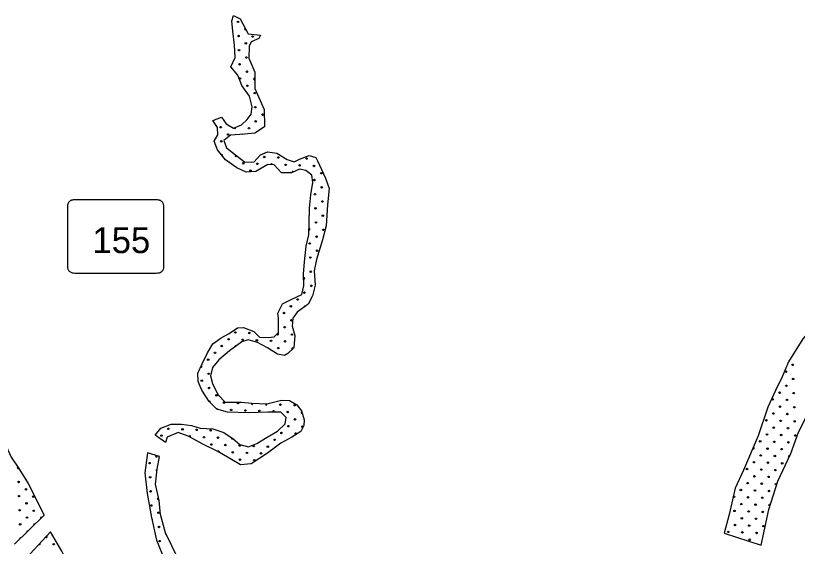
# Model space of a CAD drawing. Extents: x 1612280 to 1883141, y 560852 to 780851.
# Drawn here: x 1712819 to 1723964, y 674507 to 682075 of the extents above; entities that cross this region are included whole.
import ezdxf

# ---------------------------------------------------------------- set-up
doc = ezdxf.new("R2010")
doc.units = 0
for name, color, linetype in [('DESIGN - ROW - Slope Lines', 7, 'Continuous'), ('DESIGN - SCRATCH - User 1', 7, 'Continuous'), ('DESIGN - TRAFFIC CONTROL PERMANENT - Pavement Marking Text', 7, 'Continuous')]:
    doc.layers.add(name, color=color, linetype=linetype)

msp = doc.modelspace()

# ---------------------------------------------------------------- linework, layer by layer
at = {"layer": 'DESIGN - ROW - Slope Lines'}
msp.add_line((1713558, 679346), (1713558, 678515), dxfattribs=at)
msp.add_line((1713558, 679346), (1713558, 678515), dxfattribs=at)
for points in [[(1714931, 679336), (1714931, 679344), (1714931, 679352), (1714930, 679366), (1714929, 679377), (1714927, 679388), (1714925, 679394), (1714922, 679400), (1714917, 679408), (1714912, 679415), (1714907, 679421), (1714901, 679426), (1714897, 679430), (1714890, 679434), (1714885, 679437), (1714877, 679441), (1714871, 679444), (1714864, 679445), (1714854, 679446), (1714846, 679447), (1714837, 679448), (1714825, 679448), (1714816, 679447), (1713658, 679448), (1713649, 679448), (1713639, 679447), (1713630, 679446), (1713621, 679444), (1713616, 679443), (1713609, 679440), (1713603, 679437), (1713597, 679433), (1713588, 679427), (1713582, 679421), (1713577, 679415), (1713573, 679410), (1713568, 679400), (1713564, 679393), (1713562, 679387), (1713562, 679384), (1713561, 679380), (1713560, 679373), (1713559, 679364), (1713559, 679356), (1713559, 679349), (1713558, 679331)], [(1714931, 679336), (1714931, 679344), (1714931, 679352), (1714930, 679366), (1714929, 679377), (1714927, 679388), (1714925, 679394), (1714922, 679400), (1714917, 679408), (1714912, 679415), (1714907, 679421), (1714901, 679426), (1714897, 679430), (1714890, 679434), (1714885, 679437), (1714877, 679441), (1714871, 679444), (1714864, 679445), (1714854, 679446), (1714846, 679447), (1714837, 679448), (1714825, 679448), (1714816, 679447), (1713658, 679448), (1713649, 679448), (1713639, 679447), (1713630, 679446), (1713621, 679444), (1713616, 679443), (1713609, 679440), (1713603, 679437), (1713597, 679433), (1713588, 679427), (1713582, 679421), (1713577, 679415), (1713573, 679410), (1713568, 679400), (1713564, 679393), (1713562, 679387), (1713562, 679384), (1713561, 679380), (1713560, 679373), (1713559, 679364), (1713559, 679356), (1713559, 679349), (1713558, 679331)], [(1714821, 678405), (1714842, 678406), (1714859, 678406), (1714869, 678408), (1714882, 678413), (1714893, 678420), (1714902, 678426), (1714910, 678434), (1714916, 678442), (1714922, 678452), (1714926, 678460), (1714928, 678467), (1714930, 678474), (1714931, 678483), (1714931, 678493), (1714931, 678516), (1714931, 679336)], [(1714821, 678405), (1714842, 678406), (1714859, 678406), (1714869, 678408), (1714882, 678413), (1714893, 678420), (1714902, 678426), (1714910, 678434), (1714916, 678442), (1714922, 678452), (1714926, 678460), (1714928, 678467), (1714930, 678474), (1714931, 678483), (1714931, 678493), (1714931, 678516), (1714931, 679336)], [(1713558, 678515), (1713559, 678506), (1713559, 678495), (1713560, 678486), (1713561, 678477), (1713562, 678468), (1713565, 678460), (1713569, 678453), (1713573, 678445), (1713579, 678438), (1713584, 678432), (1713591, 678425), (1713598, 678420), (1713606, 678415), (1713615, 678411), (1713624, 678408), (1713631, 678407), (1713646, 678406), (1713665, 678405), (1714821, 678405)], [(1713558, 678515), (1713559, 678506), (1713559, 678495), (1713560, 678486), (1713561, 678477), (1713562, 678468), (1713565, 678460), (1713569, 678453), (1713573, 678445), (1713579, 678438), (1713584, 678432), (1713591, 678425), (1713598, 678420), (1713606, 678415), (1713615, 678411), (1713624, 678408), (1713631, 678407), (1713646, 678406), (1713665, 678405), (1714821, 678405)]]:
    msp.add_lwpolyline(points, dxfattribs=at)
at = {"layer": 'DESIGN - SCRATCH - User 1'}
for points in [[(1716413, 679953), (1716242, 679852), (1716105, 679842), (1715971, 679905), (1715809, 680021), (1715697, 680162), (1715651, 680285), (1715704, 680376), (1715697, 680482), (1715630, 680580), (1715753, 680626), (1715820, 680531), (1715925, 680471), (1716038, 680517), (1716119, 680594), (1716178, 680672), (1716193, 680774), (1716154, 680925), (1716045, 681080), (1715985, 681228), (1715887, 681347), (1715950, 681477), (1715939, 681653), (1715915, 681854), (1715901, 682001), (1715925, 682075), (1716020, 682029), (1716136, 681815), (1716312, 681797), (1716287, 681748), (1716178, 681702), (1716147, 681639), (1716143, 681467), (1716231, 681270), (1716231, 681034), (1716361, 680739), (1716365, 680489), (1716231, 680401), (1716084, 680383), (1715883, 680369), (1715788, 680295), (1715827, 680190), (1716080, 679989), (1716217, 679986), (1716308, 680091), (1716409, 680132)], [(1716413, 679953), (1716242, 679852), (1716105, 679842), (1715971, 679905), (1715809, 680021), (1715697, 680162), (1715651, 680285), (1715704, 680376), (1715697, 680482), (1715630, 680580), (1715753, 680626), (1715820, 680531), (1715925, 680471), (1716038, 680517), (1716119, 680594), (1716178, 680672), (1716193, 680774), (1716154, 680925), (1716045, 681080), (1715985, 681228), (1715887, 681347), (1715950, 681477), (1715939, 681653), (1715915, 681854), (1715901, 682001), (1715925, 682075), (1716020, 682029), (1716136, 681815), (1716312, 681797), (1716287, 681748), (1716178, 681702), (1716147, 681639), (1716143, 681467), (1716231, 681270), (1716231, 681034), (1716361, 680739), (1716365, 680489), (1716231, 680401), (1716084, 680383), (1715883, 680369), (1715788, 680295), (1715827, 680190), (1716080, 679989), (1716217, 679986), (1716308, 680091), (1716409, 680132)], [(1716409, 680132), (1716542, 680113), (1716691, 680023), (1716792, 679992), (1716867, 680027), (1717003, 680082), (1717101, 680050), (1717121, 680003), (1717238, 679757), (1717289, 679608), (1717265, 679378), (1717246, 679077), (1717195, 678877), (1717109, 678600), (1717074, 678435), (1717089, 678232), (1717050, 678079), (1716992, 677962), (1716835, 677849), (1716773, 677763), (1716761, 677645), (1716800, 677512), (1716785, 677340), (1716699, 677258), (1716652, 677231), (1716554, 677246), (1716409, 677340)], [(1716409, 680132), (1716542, 680113), (1716691, 680023), (1716792, 679992), (1716867, 680027), (1717003, 680082), (1717101, 680050), (1717121, 680003), (1717238, 679757), (1717289, 679608), (1717265, 679378), (1717246, 679077), (1717195, 678877), (1717109, 678600), (1717074, 678435), (1717089, 678232), (1717050, 678079), (1716992, 677962), (1716835, 677849), (1716773, 677763), (1716761, 677645), (1716800, 677512), (1716785, 677340), (1716699, 677258), (1716652, 677231), (1716554, 677246), (1716409, 677340)], [(1716418, 677486), (1716503, 677493), (1716566, 677559), (1716566, 677767), (1716558, 677833), (1716624, 677966), (1716749, 678029), (1716898, 678099), (1716929, 678220), (1716921, 678388), (1716937, 678564), (1716960, 678787), (1717000, 678951), (1717003, 679124), (1717011, 679331), (1717027, 679522), (1717058, 679698), (1717043, 679800), (1716957, 679867), (1716867, 679886), (1716753, 679835), (1716609, 679835), (1716503, 679949), (1716413, 679953)], [(1716418, 677486), (1716503, 677493), (1716566, 677559), (1716566, 677767), (1716558, 677833), (1716624, 677966), (1716749, 678029), (1716898, 678099), (1716929, 678220), (1716921, 678388), (1716937, 678564), (1716960, 678787), (1717000, 678951), (1717003, 679124), (1717011, 679331), (1717027, 679522), (1717058, 679698), (1717043, 679800), (1716957, 679867), (1716867, 679886), (1716753, 679835), (1716609, 679835), (1716503, 679949), (1716413, 679953)], [(1711026, 679078), (1711258, 678679), (1711508, 678205), (1711759, 677776), (1711915, 677502), (1712188, 676989), (1712439, 676465), (1712606, 676102), (1712757, 675779), (1712863, 675617), (1712997, 675405), (1713225, 674953), (1712801, 674541)], [(1711026, 679078), (1711258, 678679), (1711508, 678205), (1711759, 677776), (1711915, 677502), (1712188, 676989), (1712439, 676465), (1712606, 676102), (1712757, 675779), (1712863, 675617), (1712997, 675405), (1713225, 674953), (1712801, 674541)], [(1716414, 676423), (1716138, 676411), (1715839, 676422), (1715688, 676462), (1715578, 676575), (1715476, 676734), (1715421, 676859), (1715417, 676976), (1715478, 677112), (1715553, 677265), (1715631, 677397), (1715750, 677480), (1715862, 677545), (1715981, 677624), (1716066, 677628), (1716215, 677569), (1716295, 677492), (1716418, 677486)], [(1716414, 676423), (1716138, 676411), (1715839, 676422), (1715688, 676462), (1715578, 676575), (1715476, 676734), (1715421, 676859), (1715417, 676976), (1715478, 677112), (1715553, 677265), (1715631, 677397), (1715750, 677480), (1715862, 677545), (1715981, 677624), (1716066, 677628), (1716215, 677569), (1716295, 677492), (1716418, 677486)], [(1724680, 677335), (1724231, 677683), (1724040, 677467), (1723836, 677138), (1723735, 676892), (1723681, 676790), (1723543, 676491), (1723405, 676083), (1723196, 675592), (1723076, 675335), (1722992, 674963), (1722921, 674694)], [(1724680, 677335), (1724231, 677683), (1724040, 677467), (1723836, 677138), (1723735, 676892), (1723681, 676790), (1723543, 676491), (1723405, 676083), (1723196, 675592), (1723076, 675335), (1722992, 674963), (1722921, 674694)], [(1716409, 677340), (1716266, 677416), (1716134, 677450), (1716045, 677426), (1715869, 677297), (1715716, 677165), (1715627, 677059), (1715599, 676940), (1715627, 676828), (1715701, 676673), (1715807, 676564), (1716041, 676562), (1716185, 676547), (1716400, 676541)], [(1716409, 677340), (1716266, 677416), (1716134, 677450), (1716045, 677426), (1715869, 677297), (1715716, 677165), (1715627, 677059), (1715599, 676940), (1715627, 676828), (1715701, 676673), (1715807, 676564), (1716041, 676562), (1716185, 676547), (1716400, 676541)], [(1722921, 674694), (1723447, 674526), (1723555, 675035), (1723687, 675437), (1723872, 675832), (1723980, 676137), (1724136, 676443), (1724261, 676742), (1724447, 677060), (1724680, 677335)], [(1722921, 674694), (1723447, 674526), (1723555, 675035), (1723687, 675437), (1723872, 675832), (1723980, 676137), (1724136, 676443), (1724261, 676742), (1724447, 677060), (1724680, 677335)], [(1716400, 676541), (1716608, 676591), (1716726, 676586), (1716830, 676527), (1716897, 676442), (1716934, 676313), (1716928, 676229), (1716883, 676147), (1716757, 676063), (1716602, 675978), (1716408, 675838), (1716175, 675686), (1716026, 675672), (1715871, 675759), (1715694, 675866), (1715500, 675961), (1715281, 676080), (1715138, 676130), (1714980, 676065), (1714958, 675990), (1714809, 676091), (1714890, 676192), (1715039, 676251), (1715185, 676248), (1715326, 676229), (1715450, 676195), (1715632, 676184), (1715787, 676133), (1715919, 676040), (1716015, 675959), (1716138, 675925), (1716256, 675975), (1716405, 676065), (1716554, 676150), (1716664, 676254), (1716675, 676347), (1716599, 676423), (1716414, 676423)], [(1716400, 676541), (1716608, 676591), (1716726, 676586), (1716830, 676527), (1716897, 676442), (1716934, 676313), (1716928, 676229), (1716883, 676147), (1716757, 676063), (1716602, 675978), (1716408, 675838), (1716175, 675686), (1716026, 675672), (1715871, 675759), (1715694, 675866), (1715500, 675961), (1715281, 676080), (1715138, 676130), (1714980, 676065), (1714958, 675990), (1714809, 676091), (1714890, 676192), (1715039, 676251), (1715185, 676248), (1715326, 676229), (1715450, 676195), (1715632, 676184), (1715787, 676133), (1715919, 676040), (1716015, 675959), (1716138, 675925), (1716256, 675975), (1716405, 676065), (1716554, 676150), (1716664, 676254), (1716675, 676347), (1716599, 676423), (1716414, 676423)], [(1714869, 675789), (1714697, 675840), (1714660, 675557), (1714693, 675260), (1714758, 674917), (1714827, 674597), (1714938, 674328), (1715045, 674027), (1715142, 673767), (1715170, 673605), (1715133, 673461), (1715012, 673271), (1714855, 673048), (1714688, 672825), (1714592, 672614)], [(1714869, 675789), (1714697, 675840), (1714660, 675557), (1714693, 675260), (1714758, 674917), (1714827, 674597), (1714938, 674328), (1715045, 674027), (1715142, 673767), (1715170, 673605), (1715133, 673461), (1715012, 673271), (1714855, 673048), (1714688, 672825), (1714592, 672614)], [(1714739, 672459), (1714744, 672556), (1714864, 672631), (1714994, 672594), (1715045, 672621), (1714999, 672784), (1715290, 673159), (1715374, 673178), (1715439, 673275), (1715462, 673447), (1715416, 673707), (1715314, 673980), (1715138, 674328), (1714957, 674699), (1714887, 674963), (1714864, 675163), (1714813, 675395), (1714836, 675608), (1714869, 675789)], [(1714739, 672459), (1714744, 672556), (1714864, 672631), (1714994, 672594), (1715045, 672621), (1714999, 672784), (1715290, 673159), (1715374, 673178), (1715439, 673275), (1715462, 673447), (1715416, 673707), (1715314, 673980), (1715138, 674328), (1714957, 674699), (1714887, 674963), (1714864, 675163), (1714813, 675395), (1714836, 675608), (1714869, 675789)], [(1714592, 672614), (1714388, 672851), (1714220, 673096), (1714034, 673432), (1713935, 673655), (1713742, 673969), (1713581, 674232), (1713479, 674440), (1713318, 674714), (1712912, 674278)], [(1714592, 672614), (1714388, 672851), (1714220, 673096), (1714034, 673432), (1713935, 673655), (1713742, 673969), (1713581, 674232), (1713479, 674440), (1713318, 674714), (1712912, 674278)]]:
    msp.add_lwpolyline(points, dxfattribs=at)
for centre in [(1716512, 676027), (1716512, 676027), (1716415, 675930), (1716415, 675930), (1723434, 676006), (1723434, 676006), (1723635, 675998), (1723635, 675998), (1716318, 675833), (1716318, 675833)]:
    msp.add_circle(centre, 10.6, dxfattribs=at)
msp.add_arc((1712854, 675627), 10.6, 114.4375, 311.9916, dxfattribs=at)
at = {"layer": 'DESIGN - TRAFFIC CONTROL PERMANENT - Pavement Marking Text'}
for centre in [(1715989, 681986), (1715989, 681986), (1715997, 681784), (1715997, 681784), (1716198, 681777), (1716198, 681777), (1716101, 681680), (1716101, 681680), (1716004, 681583), (1716004, 681583), (1716012, 681381), (1716012, 681381), (1716109, 681478), (1716109, 681478), (1716116, 681276), (1716116, 681276), (1716019, 681179), (1716019, 681179), (1716124, 681075), (1716124, 681075), (1716228, 680970), (1716228, 680970), (1716236, 680769), (1716236, 680769), (1716340, 680664), (1716340, 680664), (1715743, 680485), (1715743, 680485), (1716243, 680567), (1716243, 680567), (1715847, 680380), (1715847, 680380), (1716146, 680470), (1716146, 680470), (1715750, 680283), (1715750, 680283), (1716363, 680059), (1716363, 680059), (1716564, 680052), (1716564, 680052), (1716967, 680037), (1716967, 680037), (1716064, 679970), (1716064, 679970), (1716265, 679962), (1716265, 679962), (1716669, 679947), (1716669, 679947), (1716870, 679940), (1716870, 679940), (1717072, 679932), (1717072, 679932), (1716168, 679865), (1716168, 679865), (1717176, 679828), (1717176, 679828), (1717079, 679731), (1717079, 679731), (1717184, 679626), (1717184, 679626), (1717087, 679529), (1717087, 679529), (1717191, 679425), (1717191, 679425), (1717094, 679327), (1717094, 679327), (1717199, 679223), (1717199, 679223), (1717102, 679126), (1717102, 679126), (1717109, 678924), (1717109, 678924), (1717206, 679021), (1717206, 679021), (1717012, 678827), (1717012, 678827), (1717117, 678723), (1717117, 678723), (1717020, 678626), (1717020, 678626), (1717027, 678424), (1717027, 678424), (1717035, 678222), (1717035, 678222), (1716840, 678028), (1716840, 678028), (1716937, 678125), (1716937, 678125), (1716743, 677931), (1716743, 677931), (1716646, 677834), (1716646, 677834), (1716751, 677730), (1716751, 677730), (1716654, 677632), (1716654, 677632), (1715952, 677558), (1715952, 677558), (1716153, 677550), (1716153, 677550), (1716758, 677528), (1716758, 677528), (1715758, 677364), (1715758, 677364), (1715855, 677461), (1715855, 677461), (1716056, 677453), (1716056, 677453), (1716258, 677446), (1716258, 677446), (1716460, 677438), (1716460, 677438), (1716661, 677431), (1716661, 677431), (1715661, 677267), (1715661, 677267), (1716564, 677334), (1716564, 677334), (1715564, 677169), (1715564, 677169), (1723897, 677096), (1723897, 677096), (1715571, 676968), (1715571, 676968), (1723800, 676999), (1723800, 676999), (1715474, 676871), (1715474, 676871), (1723904, 676895), (1723904, 676895), (1715578, 676766), (1715578, 676766), (1723710, 676700), (1723710, 676700), (1723807, 676797), (1723807, 676797), (1723912, 676693), (1723912, 676693), (1715683, 676662), (1715683, 676662), (1723613, 676603), (1723613, 676603), (1723815, 676596), (1723815, 676596), (1715788, 676557), (1715788, 676557), (1715989, 676550), (1715989, 676550), (1716594, 676527), (1716594, 676527), (1716796, 676520), (1716796, 676520), (1723718, 676499), (1723718, 676499), (1723919, 676491), (1723919, 676491), (1715892, 676453), (1715892, 676453), (1716094, 676445), (1716094, 676445), (1716295, 676438), (1716295, 676438), (1716699, 676423), (1716699, 676423), (1723620, 676402), (1723620, 676402), (1723822, 676394), (1723822, 676394), (1716803, 676318), (1716803, 676318), (1723523, 676305), (1723523, 676305), (1723725, 676297), (1723725, 676297), (1723927, 676290), (1723927, 676290), (1714996, 676184), (1714996, 676184), (1715198, 676176), (1715198, 676176), (1715399, 676169), (1715399, 676169), (1715601, 676161), (1715601, 676161), (1716706, 676221), (1716706, 676221), (1716908, 676214), (1716908, 676214), (1723628, 676200), (1723628, 676200), (1723830, 676193), (1723830, 676193), (1714899, 676087), (1714899, 676087), (1715504, 676064), (1715504, 676064), (1715705, 676057), (1715705, 676057), (1716609, 676124), (1716609, 676124), (1716811, 676117), (1716811, 676117), (1723531, 676103), (1723531, 676103), (1723733, 676096), (1723733, 676096), (1723934, 676088), (1723934, 676088), (1715608, 675960), (1715608, 675960), (1715810, 675952), (1715810, 675952), (1716012, 675945), (1716012, 675945), (1716213, 675937), (1716213, 675937), (1723837, 675991), (1723837, 675991), (1715915, 675848), (1715915, 675848), (1716116, 675840), (1716116, 675840), (1723441, 675804), (1723441, 675804), (1723538, 675901), (1723538, 675901), (1723740, 675894), (1723740, 675894), (1714729, 675695), (1714729, 675695), (1716019, 675743), (1716019, 675743), (1716221, 675736), (1716221, 675736), (1723344, 675707), (1723344, 675707), (1723546, 675700), (1723546, 675700), (1723643, 675797), (1723643, 675797), (1723747, 675692), (1723747, 675692), (1723247, 675610), (1723247, 675610), (1723449, 675603), (1723449, 675603), (1723650, 675595), (1723650, 675595), (1714737, 675493), (1714737, 675493), (1723352, 675506), (1723352, 675506), (1723553, 675498), (1723553, 675498), (1712862, 675426), (1712862, 675426), (1723255, 675409), (1723255, 675409), (1723456, 675401), (1723456, 675401), (1723658, 675394), (1723658, 675394), (1712966, 675321), (1712966, 675321), (1714744, 675292), (1714744, 675292), (1723158, 675312), (1723158, 675312), (1723359, 675304), (1723359, 675304), (1723561, 675297), (1723561, 675297), (1712869, 675224), (1712869, 675224), (1713071, 675217), (1713071, 675217), (1723060, 675214), (1723060, 675214), (1723262, 675207), (1723262, 675207), (1723464, 675200), (1723464, 675200), (1712876, 675023), (1712876, 675023), (1712974, 675120), (1712974, 675120), (1714752, 675090), (1714752, 675090), (1723165, 675110), (1723165, 675110), (1723367, 675102), (1723367, 675102), (1712981, 674918), (1712981, 674918), (1713078, 675015), (1713078, 675015), (1714856, 674986), (1714856, 674986), (1723068, 675013), (1723068, 675013), (1723172, 674908), (1723172, 674908), (1723270, 675005), (1723270, 675005), (1723471, 674998), (1723471, 674998), (1712884, 674821), (1712884, 674821), (1723075, 674811), (1723075, 674811), (1723277, 674804), (1723277, 674804), (1723374, 674901), (1723374, 674901), (1723479, 674796), (1723479, 674796), (1714864, 674784), (1714864, 674784), (1722978, 674714), (1722978, 674714), (1723180, 674707), (1723180, 674707), (1723382, 674699), (1723382, 674699), (1714871, 674582), (1714871, 674582), (1723284, 674602), (1723284, 674602), (1713363, 674538), (1713363, 674538)]:
    msp.add_circle(centre, 10.6, dxfattribs=at)
for centre, start, end in [((1716094, 681881), 84.3496, 332.4438), ((1716221, 681172), 5.2999, 354.7001), ((1715638, 680589), 232.7026, 348.0765), ((1715944, 680477), 193.7479, 30.4978), ((1716049, 680373), 54.0463, 133.9915), ((1715855, 680179), 194.9159, 268.3119), ((1715758, 680082), 322.7449, 114.5369), ((1715959, 680074), 87.4495, 15.7783), ((1715862, 679977), 352.1645, 116.4891), ((1716467, 679955), 332.6888, 202.3307), ((1716773, 679843), 31.5397, 196.7846), ((1717288, 679522), 137.3384, 211.0555), ((1716997, 679230), 344.5707, 11.11), ((1717005, 679029), 250.1288, 107.2684), ((1716930, 678327), 239.7158, 125.6065), ((1716945, 677924), 55.9761, 195.9458), ((1716557, 677535), 159.4762, 114.0268), ((1715959, 677356), 70.0668, 182.5991), ((1716766, 677326), 27.557, 239.8108), ((1716669, 677229), 99.56, 140.9861), ((1715466, 677072), 213.5725, 97.6995), ((1715586, 676565), 322.4936, 126.3771), ((1716191, 676542), 149.8133, 25.2568), ((1716392, 676535), 142.0437, 36.7005), ((1715690, 676460), 353.4157, 134.3091), ((1716497, 676430), 314.2169, 225.7831), ((1716900, 676415), 80.2935, 311.2476), ((1715302, 676072), 313.435, 169.9324), ((1715907, 676049), 148.6909, 321.1278), ((1715713, 675855), 324.9729, 152.8023), ((1723337, 675909), 216.675, 97.1232), ((1714826, 675792), 105.983, 40.8799), ((1723845, 675789), 22.6544, 287.055), ((1714834, 675591), 80.3149, 267.2852), ((1723150, 675513), 296.1365, 14.0049), ((1714849, 675187), 34.6654, 350.1354), ((1723568, 675095), 36.6728, 286.9923), ((1713183, 674911), 50.0766, 218.4327), ((1722971, 674916), 309.233, 20.9218), ((1713086, 674814), 59.9516, 208.5577), ((1714759, 674889), 307.2654, 77.2473), ((1712988, 674716), 70.3369, 198.1724), ((1712891, 674619), 81.7554, 186.7539), ((1713258, 674642), 198.1324, 75.8705), ((1714968, 674680), 125.3225, 286.6257), ((1713161, 674545), 225.352, 48.6509)]:
    msp.add_arc(centre, 10.6, start, end, dxfattribs=at)

# ---------------------------------------------------------------- texts
at = {"layer": 'DESIGN - ROW - Slope Lines'}
msp.add_text('155', height=369.6, rotation=0.0012, dxfattribs=at).set_placement((1713914, 678689))
msp.add_text('155', height=369.6, rotation=0.0012, dxfattribs=at).set_placement((1713914, 678689))

doc.saveas('drawing.dxf')
